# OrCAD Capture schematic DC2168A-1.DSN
size Custom; title: 50 OHM GAIN BLOCK; rev: 1; company: TM
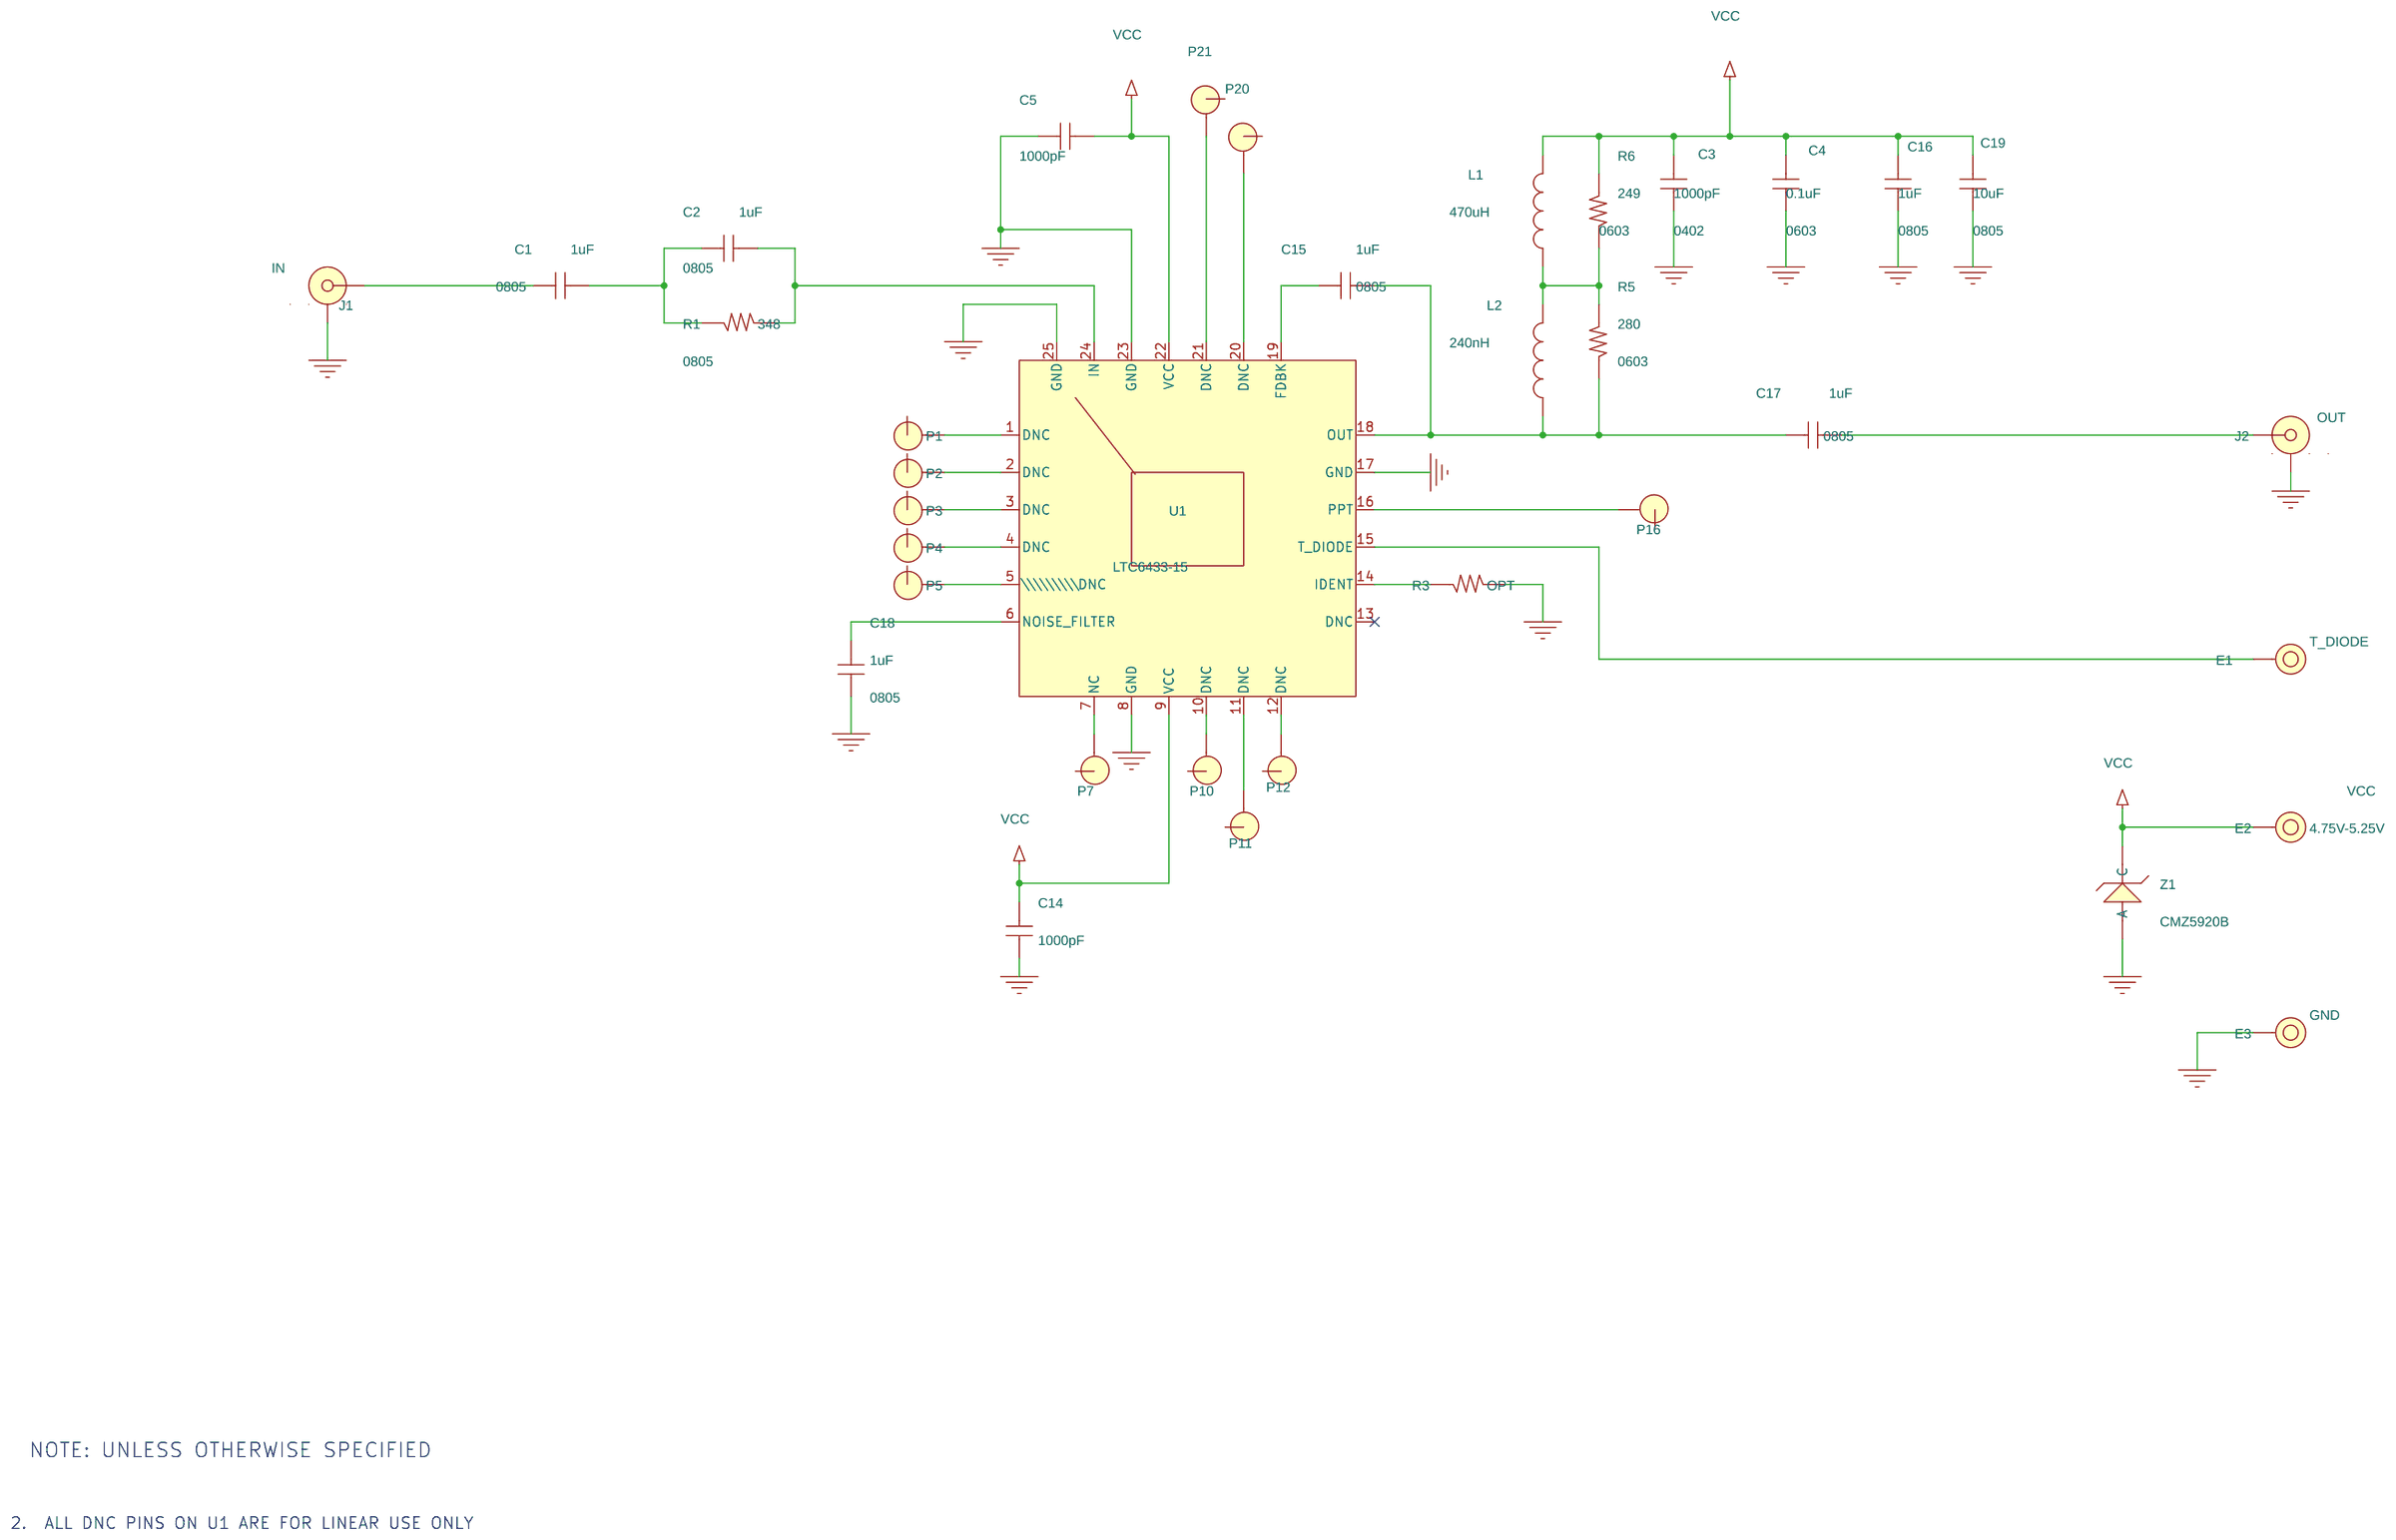
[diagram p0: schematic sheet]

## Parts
C1  1uF  [0805]
C2  1uF  [0805]
C3  1000pF  [0402]
C4  0.1uF  [0603]
C5  1000pF  [0402]
C14  1000pF  [0402]
C15  1uF  [0805]
C16  1uF  [0805]
C17  1uF  [0805]
C18  1uF  [0805]
C19  10uF  [0805]
E1  T_DIODE  [MM/2501]
E2  VCC  [MM/2501]
E3  GND  [MM/2501]
J1  IN  [CON\SMA-END]
J2  OUT  [CON\SMA-END]
L1  470uH  [IND-LPS5030]
L2  240nH  [L-0603LS-1608]
P1  T/H-PAD  [PAD-15X30]
P2  T/H-PAD  [PAD-15X30]
P3  T/H-PAD  [PAD-15X30]
P4  T/H-PAD  [PAD-15X30]
P5  T/H-PAD  [PAD-15X30]
P7  T/H-PAD  [PAD-15X30]
P10  T/H-PAD  [PAD-15X30]
P11  T/H-PAD  [PAD-15X30]
P12  T/H-PAD  [PAD-15X30]
P16  T/H-PAD  [PAD-15X30]
P20  T/H-PAD  [PAD-15X30]
P21  T/H-PAD  [PAD-15X30]
R1  348  [0805]
R3  OPT  [0402]
R5  280  [0603]
R6  249  [0603]
U1  LTC6433-15  [QFN24UF-4X4]
Z1  CMZ5920B  [DIODE-SMA]

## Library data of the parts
C1-C5 C14-C19 = CAP-NP
E1 E3 = CON_KEY_575-4_0
E2 = CON_KEY_575-4_0: 5th Part Field: 4.75V-5.25V
J1 J2 = CON_SMA-END_3: CONN, BNC, SMA 50-OHM EDGE-LANCH; 1 FILD: 50 Ohm; 2 FILD: 30MHz-3000MHz; Part Number: E.F.JOHNSON, 142-0701-851
L1 L2 = INDUCTOR
P1-P5 P7 P10-P12 P16 P20 P21 = T_H-PAD_0
R1 = R
R3 R5 = R: 1st Part Field: 0
R6 = R: 1st Part Field: 0; OPT: 250
U1 = LTC643XCUF-QFN24UF-4X4_9
Z1 = ZENER_12V_DDZ9699T_SOD523

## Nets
GND: C3.1 C4.1 C5.1 C14.1 C16.1 C18.1 C19.1 E3.1 J1.2(GND) J1.3(GND) J1.4(GND) J1.5(GND) J2.2(GND) J2.3(GND) J2.4(GND) J2.5(GND) R3.2 U1.8(GND) U1.17(GND) U1.23(GND) U1.25(GND) Z1.2(A)
VCC: C3.2 C4.2 C5.2 C14.2 C16.2 C19.2 E2.1 L1.2 R6.2 U1.9(VCC) U1.22(VCC) Z1.1(C)
N16960677: P7.1 U1.7(NC)
N16960982: C1.2 C2.1 R1.1
N16961027: C2.2 R1.2 U1.24(IN)
N16961165: P21.1 U1.21(DNC)
N16961179: P20.1 U1.20(DNC)
N16961189: C15.1 U1.19(FDBK)
N17574599: P1.1 U1.1(DNC)
N17574879: P2.1 U1.2(DNC)
N17575161: P3.1 U1.3(DNC)
N17575445: P4.1 U1.4(DNC)
N17575731: P5.1 U1.5(\\\\\\\\\DNC)
N17634065: L1.1 L2.2 R5.2 R6.1
N17650999: C15.2 C17.1 L2.1 R5.1 U1.18(OUT)
N17661728: P10.1 U1.10(DNC)
N17661948: P11.1 U1.11(DNC)
N17662170: P12.1 U1.12(DNC)
N17699615: C1.1 J1.1(CENTER)
N17883999: C17.2 J2.1(CENTER)
N17884245: E1.1 U1.15(T_DIODE)
N17885376: C18.2 U1.6(NOISE_FILTER)
N17885507: R3.1 U1.14(IDENT)
N17887930: P16.1 U1.16(PPT)

Not connected (* = marked no-connect by the designer): U1 13(DNC)*

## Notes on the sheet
- NOTE: UNLESS OTHERWISE SPECIFIED
- 2.  ALL DNC PINS ON U1 ARE FOR LINEAR USE ONLY
